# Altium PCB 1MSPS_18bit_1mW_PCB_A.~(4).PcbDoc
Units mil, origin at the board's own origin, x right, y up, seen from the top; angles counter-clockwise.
Board outline 3200 x 1700 mil, 4 copper layers (Top, Inner Layer 2, Inner Layer 3, Bottom), stack 35.4 mil thick; 66 components, 41 nets, 208 pads, 43 vias.
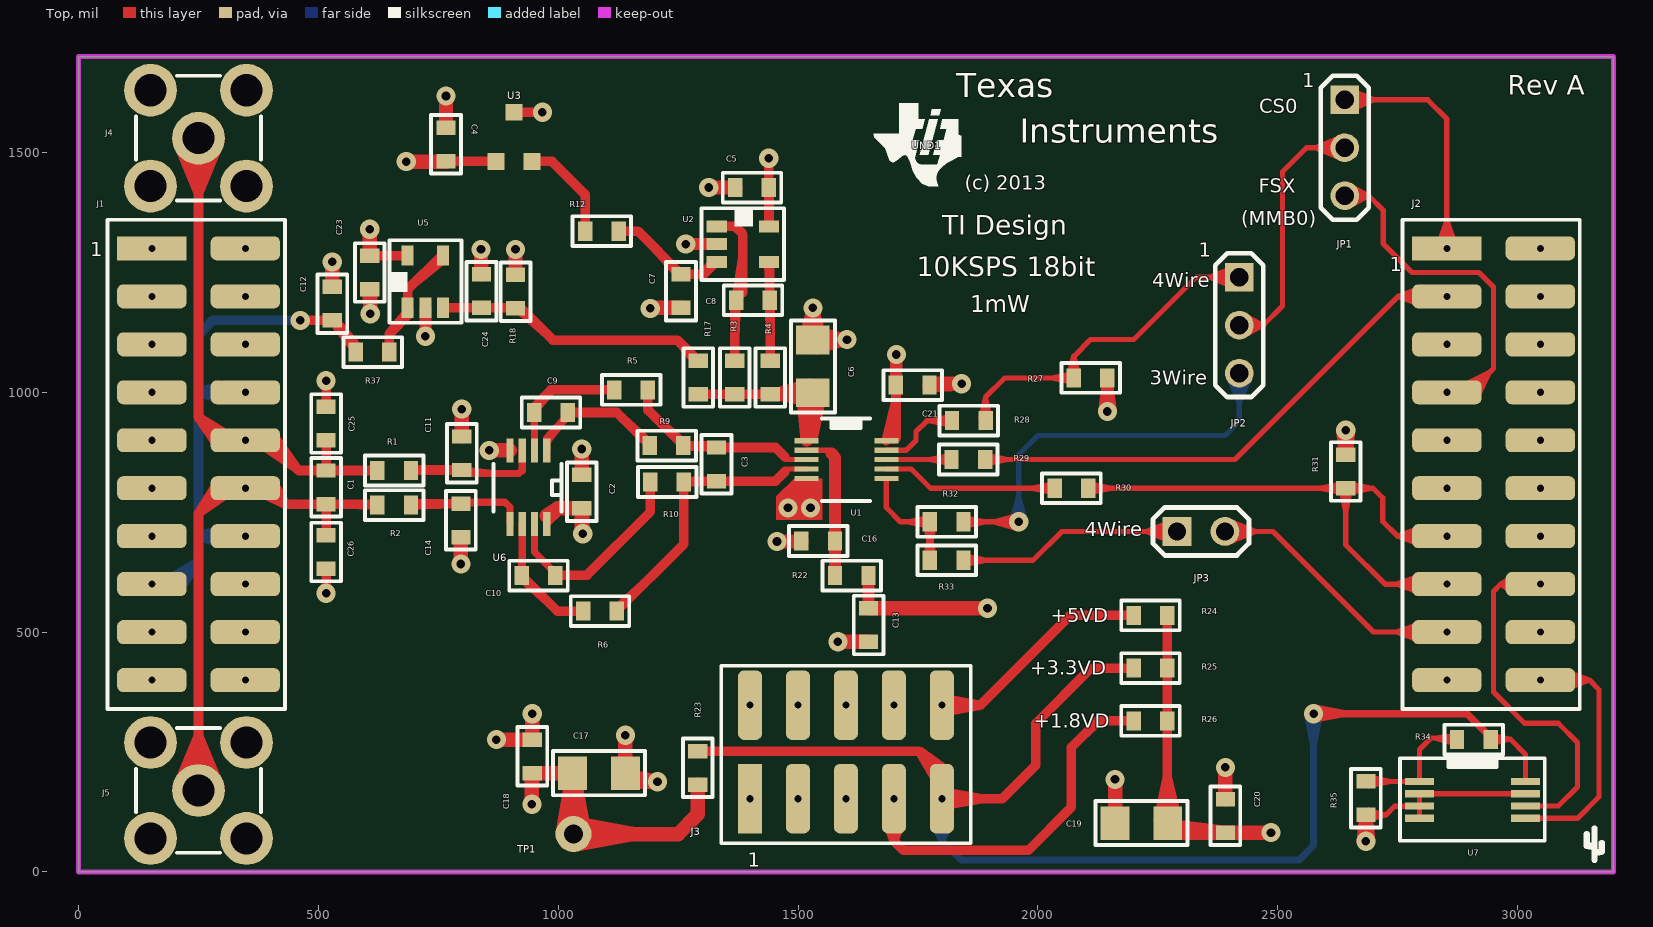
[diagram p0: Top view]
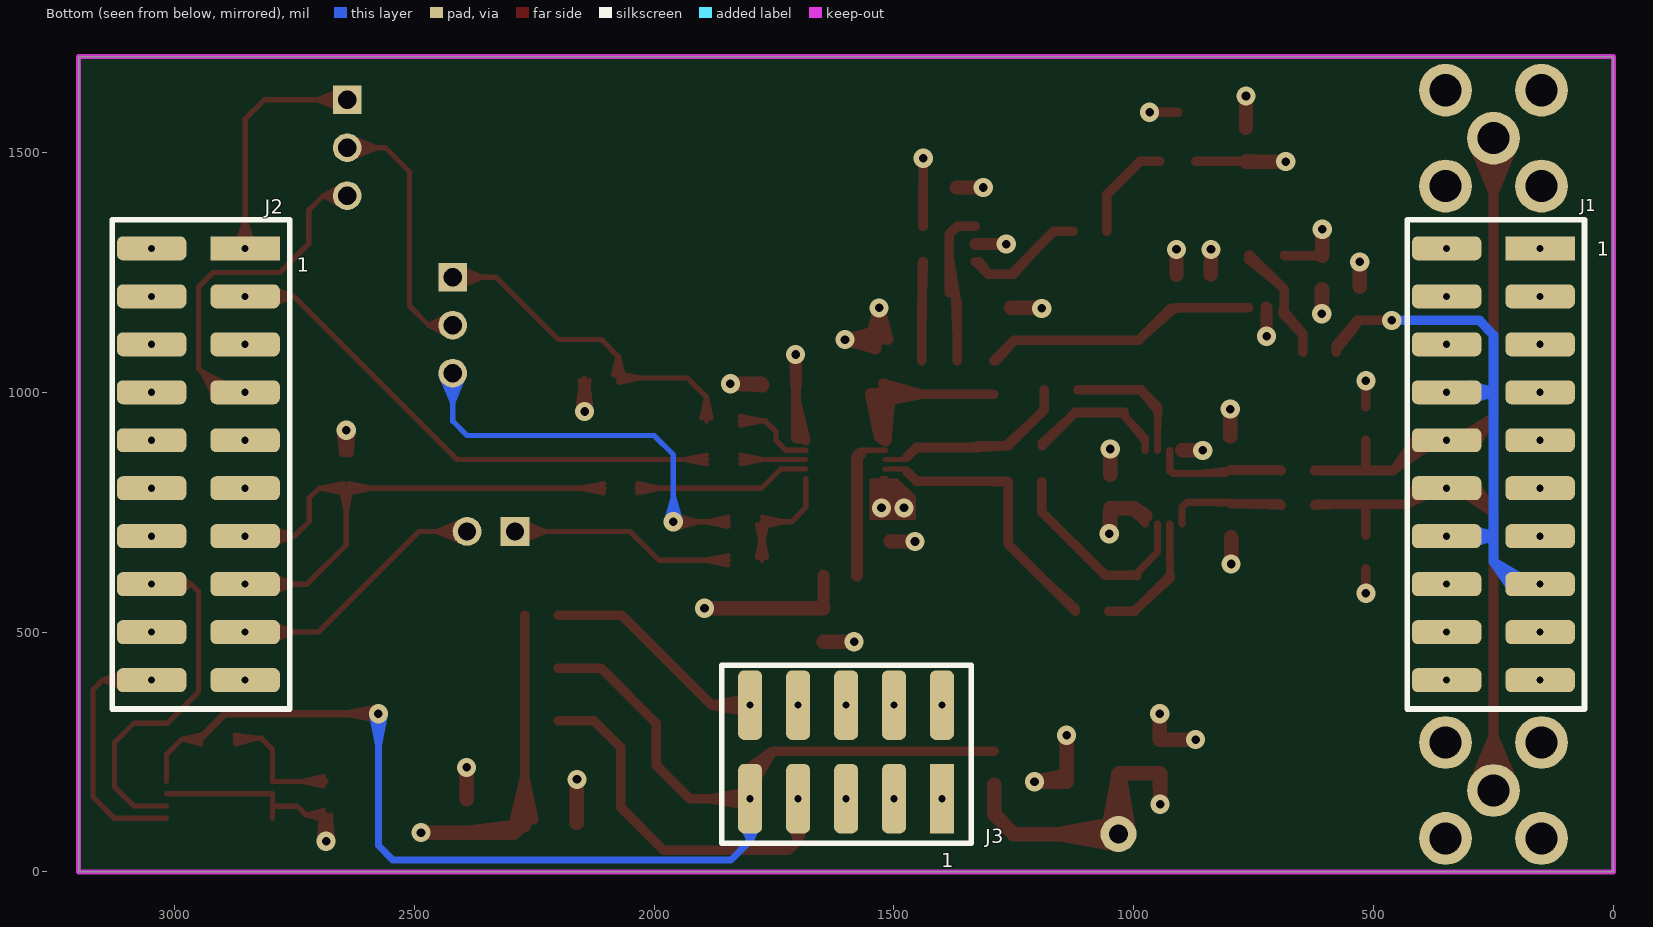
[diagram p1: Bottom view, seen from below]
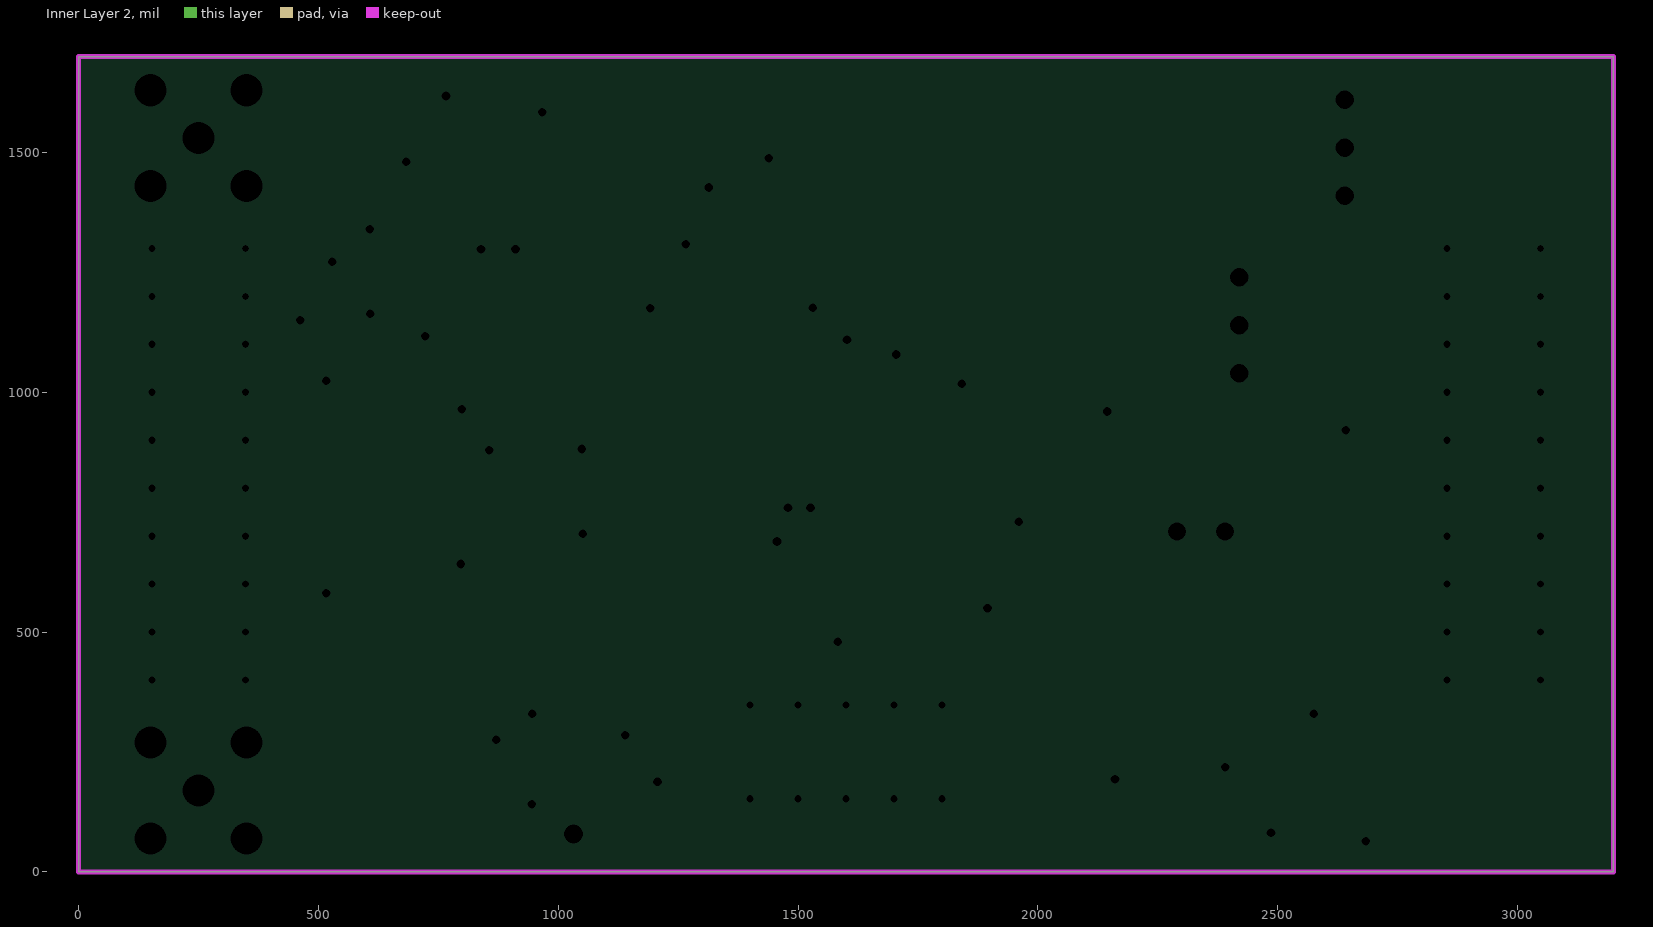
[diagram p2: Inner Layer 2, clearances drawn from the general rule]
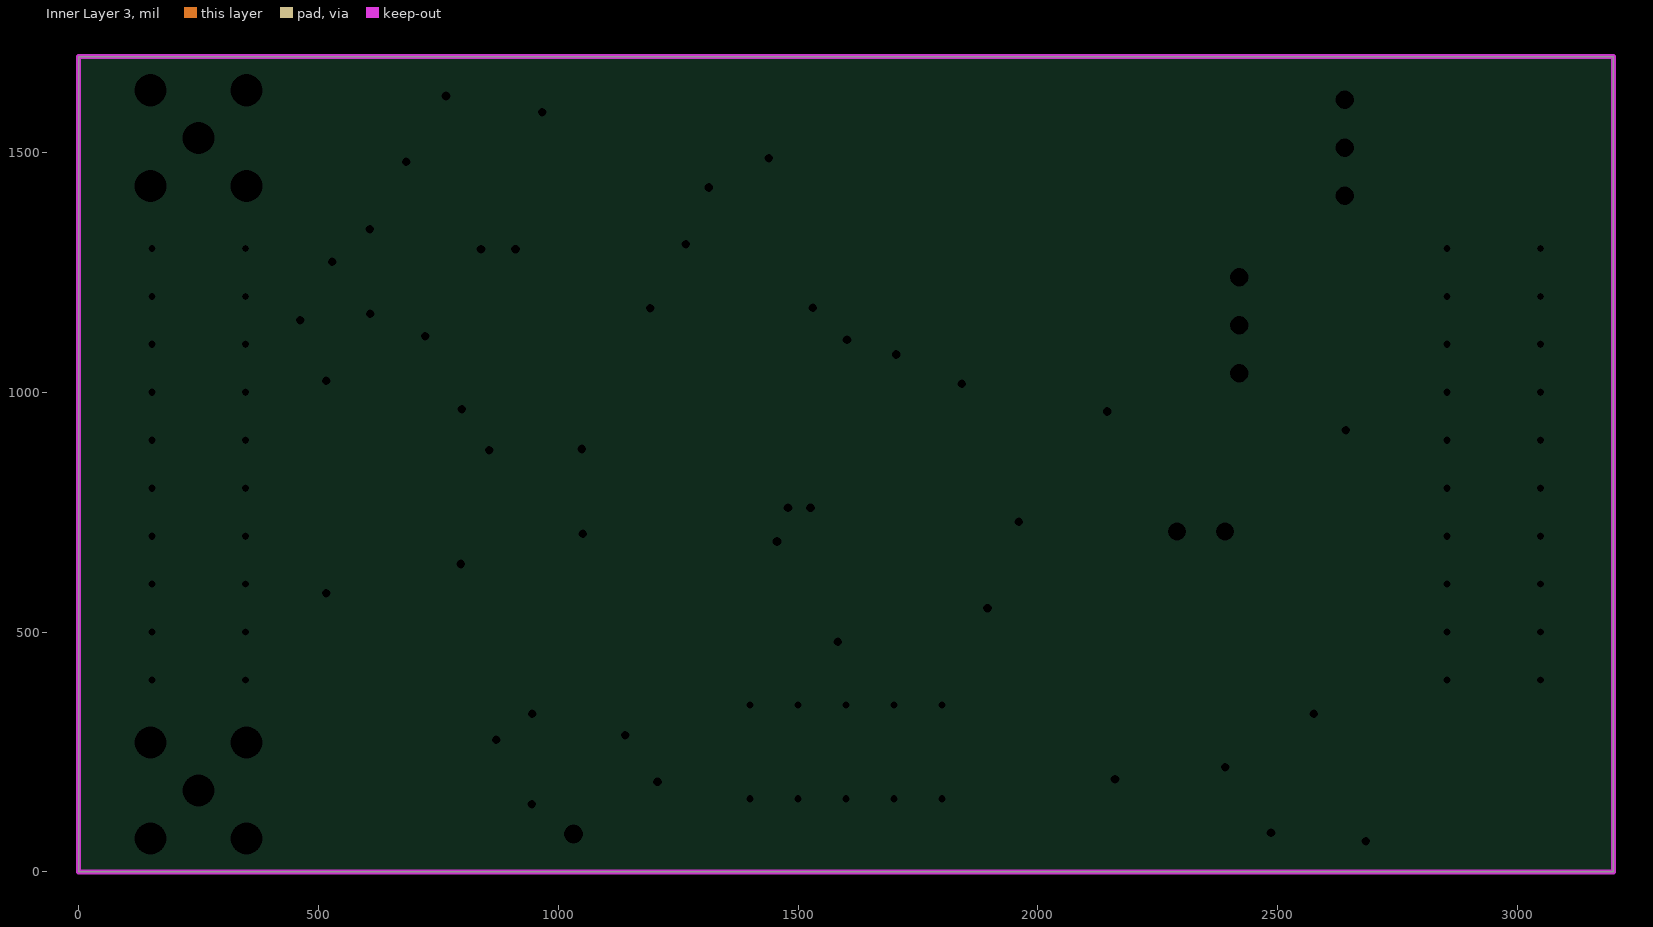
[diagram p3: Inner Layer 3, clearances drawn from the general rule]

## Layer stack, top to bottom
Top: signal copper 1.35
Dielectric: dielectric 10, FR-4, Dk 4.3
Inner Layer 2: plane copper 1.35
Dielectric: dielectric 10, FR-4, Dk 4.3
Inner Layer 3: plane copper 1.35
Dielectric: dielectric 10, FR-4, Dk 4.3
Bottom: signal copper 1.35

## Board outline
0,0 3200,0 3200,1700 0,1700

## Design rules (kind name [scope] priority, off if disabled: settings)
Clearance "'Default' PADS rule_18" [All] p1: gap=7
Clearance "'Default' PADS rule_15" [IsVia vs IsVia] p2: gap=7
ComponentClearance "'Default' PADS rule_12" [All] p1: gap=7 collisioncheckmode=3 verticalgap=10 showdistances=FALSE
FlightTimeFalling "'Default' PADS rule_10" [All] p1: maximum=10.00
FlightTimeRising "'Default' PADS rule_9" [All] p1: maximum=10.00
Length "'Default' PADS rule_5" [All] p1: maxlimit=50000 minlimit=0
MatchedLengths "'Default' PADS rule_11" [InNetClass('All Nets')] p1: tolerance=200 checknetsindiffpair=TRUE checkdiffpairvsdiffpair=TRUE checkothers=TRUE
MaxMinImpedance "'Default' PADS rule_8" [All] p1: minimum=50.00 maximum=150.0
ParallelSegment "'Default' PADS rule_7" [All] p1: limit=1000 gap=200
ParallelSegment "'Default' PADS rule_6" [All] p2: limit=1000 gap=200
PlaneClearance "'Default' PADS rule_14" [All] p1: clearance=7
PlaneConnect "Power Plane Connect Style for STDPCADVIA" [IsVia And (ViaDiameter=40) And (HoleSize=18)] p1: planeconnectstyle=Relief reliefexpansion=11 reliefentries=4 reliefconductorwidth=10 reliefairgap=10
PlaneConnect "Power Plane Connect Style for J3-5" [(Name='J3-5')] p2: planeconnectstyle=Relief reliefexpansion=7.5 reliefentries=4 reliefconductorwidth=20 reliefairgap=5
PlaneConnect "Power Plane Connect Style - pads with no thermal" [(Name='J2-2') Or (Name='J2-5') Or (Name='J2-6') Or (Name='J2-8') Or (Name='J2-9') Or (Name='J2-11') Or (Name='J2-12') Or (Name='J2-14') Or (Name='J2-19') Or (Name='J3-1') Or (Name='J3-2') Or (Name='J3-3') Or (Name='J3-4') Or (Name='J3-8') Or (Name='TP1-1')] p3: planeconnectstyle=NoConnect reliefexpansion=20 reliefentries=4 reliefconductorwidth=10 reliefairgap=10 // PAD - No Thermal Connect Rule
PlaneConnect "Power Plane Connect Style for J1-1" [(Name='J1-1')] p4: planeconnectstyle=Relief reliefexpansion=17.5 reliefentries=4 reliefconductorwidth=10 reliefairgap=10
PlaneConnect "Power Plane Connect Style - Via from round thru-hole global defaults" [IsVia] p5: planeconnectstyle=Relief reliefexpansion=20 reliefentries=4 reliefconductorwidth=10 reliefairgap=10
PlaneConnect "Power Plane Connect Style - Round thru-hole pad from global defaults" [IsPad And OnMultiLayer And (PadShape_MidLayer1 = 'Round') And (PadXSize_MidLayer1 = PadYSize_MidLayer1)] p6: planeconnectstyle=Relief reliefexpansion=20 reliefentries=4 reliefconductorwidth=10 reliefairgap=10
PlaneConnect "Power Plane Connect Style - Square thru-hole pad from global defaults" [IsPad And OnMultiLayer And ((PadShape_MidLayer1 = 'Rectangular') Or (PadShape_MidLayer1 = 'Octagonal') Or (PadShape_MidLayer1 = 'Rounded Rectangle')) And (PadXSize_MidLayer1 = PadYSize_MidLayer1)] p7: planeconnectstyle=Direct reliefexpansion=20 reliefentries=4 reliefconductorwidth=10 reliefairgap=10
PlaneConnect "Power Plane Connect Style - Rect thru-hole pad from global defaults" [IsPad And OnMultiLayer And ((PadShape_MidLayer1 = 'Rectangular') Or (PadShape_MidLayer1 = 'Octagonal') Or (PadShape_MidLayer1 = 'Rounded Rectangle')) And (PadXSize_MidLayer1 <> PadYSize_MidLayer1)] p8: planeconnectstyle=Direct reliefexpansion=20 reliefentries=4 reliefconductorwidth=10 reliefairgap=10
PlaneConnect "Power Plane Connect Style - Square-rect thru-hole pad from global defaults" [IsPad And OnMultiLayer And (PadShape_MidLayer1 = 'Rounded Rectangle') And (PadXSize_MidLayer1 = PadYSize_MidLayer1) And (Pad_CornerRadius_MidLayer1 = '0%')] p9: planeconnectstyle=Direct reliefexpansion=20 reliefentries=4 reliefconductorwidth=10 reliefairgap=10
PlaneConnect "Power Plane Connect Style - Oval thru-hole pad from global defaults" [IsPad And OnMultiLayer And (PadShape_MidLayer1 = 'Round') And (PadXSize_MidLayer1 <> PadYSize_MidLayer1)] p10: planeconnectstyle=Direct reliefexpansion=20 reliefentries=4 reliefconductorwidth=10 reliefairgap=10
PlaneConnect "Power Plane Connect Style - Round-oval thru-hole pad from global defaults" [IsPad And OnMultiLayer And (PadShape_MidLayer1 = 'Rounded Rectangle') And (PadXSize_MidLayer1 = PadYSize_MidLayer1) And (Pad_CornerRadius_MidLayer1 = '100%')] p11: planeconnectstyle=Direct reliefexpansion=20 reliefentries=4 reliefconductorwidth=10 reliefairgap=10
PolygonConnect "Polygon Connect Style - Bottom Round SMD from global defaults" [IsSMTPin And (PadShape_BottomLayer = 'Round') And (PadXSize_BottomLayer = PADYSize_BottomLayer) vs Layer = 'Bottom'] p1: connectstyle=Direct reliefconductorwidth=10 reliefentries=4 polygonreliefangle="45 Angle" airgapwidth=10
PolygonConnect "Polygon Connect Style - Top Round SMD from global defaults" [IsSMTPin And (PadShape_TopLayer = 'Round') And (PadXSize_TopLayer = PADYSize_TopLayer) vs Layer = 'Top'] p2: connectstyle=Direct reliefconductorwidth=10 reliefentries=4 polygonreliefangle="45 Angle" airgapwidth=10
PolygonConnect "Polygon Connect Style - Bottom Square SMD from global defaults 1" [IsSMTPin And (PadShape_BottomLayer = 'Rectangular') And (PadXSize_BottomLayer = PADYSize_BottomLayer) vs Layer = 'Bottom'] p3: connectstyle=Direct reliefconductorwidth=10 reliefentries=4 polygonreliefangle="45 Angle" airgapwidth=10
PolygonConnect "Polygon Connect Style - Bottom Square SMD from global defaults 2" [IsSMTPin And (PadShape_BottomLayer = 'Octagonal') And (PadXSize_BottomLayer = PADYSize_BottomLayer) vs Layer = 'Bottom'] p4: connectstyle=Direct reliefconductorwidth=10 reliefentries=4 polygonreliefangle="45 Angle" airgapwidth=10
PolygonConnect "Polygon Connect Style - Bottom Square SMD from global defaults 3" [IsSMTPin And (PadShape_BottomLayer = 'Rounded Rectangle') And (PadXSize_BottomLayer = PADYSize_BottomLayer) vs Layer = 'Bottom'] p5: connectstyle=Direct reliefconductorwidth=10 reliefentries=4 polygonreliefangle="45 Angle" airgapwidth=10
PolygonConnect "Polygon Connect Style - Top Square SMD from global defaults 1" [IsSMTPin And (PadShape_TopLayer = 'Rectangular') And (PadXSize_TopLayer = PADYSize_TopLayer) vs Layer = 'Top'] p6: connectstyle=Direct reliefconductorwidth=10 reliefentries=4 polygonreliefangle="45 Angle" airgapwidth=10
PolygonConnect "Polygon Connect Style - Top Square SMD from global defaults 2" [IsSMTPin And (PadShape_TopLayer = 'Octagonal') And (PadXSize_TopLayer = PADYSize_TopLayer) vs Layer = 'Top'] p7: connectstyle=Direct reliefconductorwidth=10 reliefentries=4 polygonreliefangle="45 Angle" airgapwidth=10
PolygonConnect "Polygon Connect Style - Top Square SMD from global defaults 3" [IsSMTPin And (PadShape_TopLayer = 'Rounded Rectangle') And (PadXSize_TopLayer = PADYSize_TopLayer) vs Layer = 'Top'] p8: connectstyle=Direct reliefconductorwidth=10 reliefentries=4 polygonreliefangle="45 Angle" airgapwidth=10
PolygonConnect "Polygon Connect Style - Bottom Rect SMD from global defaults 1" [IsSMTPin And (PadShape_BottomLayer = 'Rectangular') And (PadXSize_BottomLayer <> PADYSize_BottomLayer) vs Layer = 'Bottom'] p9: connectstyle=Direct reliefconductorwidth=10 reliefentries=4 polygonreliefangle="45 Angle" airgapwidth=10
PolygonConnect "Polygon Connect Style - Bottom Rect SMD from global defaults 2" [IsSMTPin And (PadShape_BottomLayer = 'Octagonal') And (PadXSize_BottomLayer <> PADYSize_BottomLayer) vs Layer = 'Bottom'] p10: connectstyle=Direct reliefconductorwidth=10 reliefentries=4 polygonreliefangle="45 Angle" airgapwidth=10
PolygonConnect "Polygon Connect Style - Bottom Rect SMD from global defaults 3" [IsSMTPin And (PadShape_BottomLayer = 'Rounded Rectangle') And (PadXSize_BottomLayer <> PADYSize_BottomLayer) vs Layer = 'Bottom'] p11: connectstyle=Direct reliefconductorwidth=10 reliefentries=4 polygonreliefangle="45 Angle" airgapwidth=10
PolygonConnect "Polygon Connect Style - Bottom Square-rect SMD pad from global defaults" [IsSMTPin And (PadShape_BottomLayer = 'Rounded Rectangle') And (PadXSize_BottomLayer = PADYSize_BottomLayer) And (Pad_CornerRadius_BottomLayer = '0%') vs Layer = 'Bottom'] p12: connectstyle=Direct reliefconductorwidth=10 reliefentries=4 polygonreliefangle="45 Angle" airgapwidth=10
PolygonConnect "Polygon Connect Style - Top Rect SMD from global defaults 1" [IsSMTPin And (PadShape_TopLayer = 'Rectangular') And (PadXSize_TopLayer <> PADYSize_TopLayer) vs Layer = 'Top'] p13: connectstyle=Direct reliefconductorwidth=10 reliefentries=4 polygonreliefangle="45 Angle" airgapwidth=10
PolygonConnect "Polygon Connect Style - Top Rect SMD from global defaults 2" [IsSMTPin And (PadShape_TopLayer = 'Octagonal') And (PadXSize_TopLayer <> PADYSize_TopLayer) vs Layer = 'Top'] p14: connectstyle=Direct reliefconductorwidth=10 reliefentries=4 polygonreliefangle="45 Angle" airgapwidth=10
PolygonConnect "Polygon Connect Style - Top Rect SMD from global defaults 3" [IsSMTPin And (PadShape_TopLayer = 'Rounded Rectangle') And (PadXSize_TopLayer <> PADYSize_TopLayer) vs Layer = 'Top'] p15: connectstyle=Direct reliefconductorwidth=10 reliefentries=4 polygonreliefangle="45 Angle" airgapwidth=10
PolygonConnect "Polygon Connect Style - Top Square-rect SMD pad from global defaults" [IsSMTPin And (PadShape_TopLayer = 'Rounded Rectangle') And (PadXSize_TopLayer = PADYSize_TopLayer) And (Pad_CornerRadius_TopLayer = '0%') vs Layer = 'Top'] p16: connectstyle=Direct reliefconductorwidth=10 reliefentries=4 polygonreliefangle="45 Angle" airgapwidth=10
PolygonConnect "Polygon Connect Style - Bottom Oval SMD from global defaults" [IsSMTPin And (PadShape_BottomLayer = 'Round') And (PadXSize_BottomLayer <> PADYSize_BottomLayer) vs Layer = 'Bottom'] p17: connectstyle=Direct reliefconductorwidth=10 reliefentries=4 polygonreliefangle="45 Angle" airgapwidth=10
PolygonConnect "Polygon Connect Style - Bottom Round-oval SMD pad from global defaults" [IsSMTPin And (PadShape_BottomLayer = 'Rounded Rectangle') And (PadXSize_BottomLayer = PADYSize_BottomLayer) And (Pad_CornerRadius_BottomLayer = '100%') vs Layer = 'Bottom'] p18: connectstyle=Direct reliefconductorwidth=10 reliefentries=4 polygonreliefangle="45 Angle" airgapwidth=10
PolygonConnect "Polygon Connect Style - Top Oval SMD from global defaults" [IsSMTPin And (PadShape_TopLayer = 'Round') And (PadXSize_TopLayer <> PADYSize_TopLayer) vs Layer = 'Top'] p19: connectstyle=Direct reliefconductorwidth=10 reliefentries=4 polygonreliefangle="45 Angle" airgapwidth=10
PolygonConnect "Polygon Connect Style - Top Round-oval SMD pad from global defaults" [IsSMTPin And (PadShape_TopLayer = 'Rounded Rectangle') And (PadXSize_TopLayer = PADYSize_TopLayer) And (Pad_CornerRadius_TopLayer = '100%') vs Layer = 'Top'] p20: connectstyle=Direct reliefconductorwidth=10 reliefentries=4 polygonreliefangle="45 Angle" airgapwidth=10
PolygonConnect "Polygon Connect Style - Via from round thru-hole global defaults_19" [IsVia] p21: connectstyle=Relief reliefconductorwidth=10 reliefentries=4 polygonreliefangle="90 Angle" airgapwidth=10
PolygonConnect "Polygon Connect Style - Bottom Round thru-hole pad from global defaults" [IsPad And OnMultiLayer And (PadShape_BottomLayer = 'Round') And (PadXSize_BottomLayer = PADYSize_BottomLayer) vs Layer = 'Bottom'] p22: connectstyle=Relief reliefconductorwidth=10 reliefentries=4 polygonreliefangle="90 Angle" airgapwidth=10
PolygonConnect "Polygon Connect Style - Via from round thru-hole global defaults" [IsVia] p23: connectstyle=Relief reliefconductorwidth=10 reliefentries=4 polygonreliefangle="90 Angle" airgapwidth=10
PolygonConnect "Polygon Connect Style - Top Round thru-hole pad from global defaults" [IsPad And OnMultiLayer And (PadShape_TopLayer = 'Round') And (PadXSize_TopLayer = PADYSize_TopLayer) vs Layer = 'Top'] p24: connectstyle=Relief reliefconductorwidth=10 reliefentries=4 polygonreliefangle="90 Angle" airgapwidth=10
PolygonConnect "Polygon Connect Style - Bottom Square thru-hole pad from global defaults" [IsPad And OnMultiLayer And ((PadShape_BottomLayer = 'Rectangular') Or (PadShape_BottomLayer = 'Octagonal') Or (PadShape_BottomLayer = 'Rounded Rectangle')) And (PadXSize_BottomLayer = PADYSize_BottomLayer) vs Layer = 'Bottom'] p25: connectstyle=Direct reliefconductorwidth=10 reliefentries=4 polygonreliefangle="45 Angle" airgapwidth=10
PolygonConnect "Polygon Connect Style - Top Square thru-hole pad from global defaults" [IsPad And OnMultiLayer And ((PadShape_TopLayer = 'Rectangular') Or (PadShape_TopLayer = 'Octagonal') Or (PadShape_TopLayer = 'Rounded Rectangle')) And (PadXSize_TopLayer = PADYSize_TopLayer) vs Layer = 'Top'] p26: connectstyle=Direct reliefconductorwidth=10 reliefentries=4 polygonreliefangle="45 Angle" airgapwidth=10
PolygonConnect "Polygon Connect Style - Bottom Rect thru-hole pad from global defaults" [IsPad And OnMultiLayer And ((PadShape_BottomLayer = 'Rectangular') Or (PadShape_BottomLayer = 'Octagonal') Or (PadShape_BottomLayer = 'Rounded Rectangle')) And (PadXSize_BottomLayer <> PADYSize_BottomLayer) vs Layer = 'Bottom'] p27: connectstyle=Direct reliefconductorwidth=10 reliefentries=4 polygonreliefangle="45 Angle" airgapwidth=10
PolygonConnect "Polygon Connect Style - Bottom Square-rect thru-hole pad from global defaults" [IsPad And OnMultiLayer And (PadShape_BottomLayer = 'Rounded Rectangle') And (PadXSize_BottomLayer = PADYSize_BottomLayer) And (Pad_CornerRadius_BottomLayer = '0%') vs Layer = 'Bottom'] p28: connectstyle=Direct reliefconductorwidth=10 reliefentries=4 polygonreliefangle="45 Angle" airgapwidth=10
PolygonConnect "Polygon Connect Style - Top Rect thru-hole pad from global defaults" [IsPad And OnMultiLayer And ((PadShape_TopLayer = 'Rectangular') Or (PadShape_TopLayer = 'Octagonal') Or (PadShape_TopLayer = 'Rounded Rectangle')) And (PadXSize_TopLayer <> PADYSize_TopLayer) vs Layer = 'Top'] p29: connectstyle=Direct reliefconductorwidth=10 reliefentries=4 polygonreliefangle="45 Angle" airgapwidth=10
PolygonConnect "Polygon Connect Style - Top Square-rect thru-hole pad from global defaults" [IsPad And OnMultiLayer And (PadShape_TopLayer = 'Rounded Rectangle') And (PadXSize_TopLayer = PADYSize_TopLayer) And (Pad_CornerRadius_TopLayer = '0%') vs Layer = 'Top'] p30: connectstyle=Direct reliefconductorwidth=10 reliefentries=4 polygonreliefangle="45 Angle" airgapwidth=10
PolygonConnect "Polygon Connect Style - Bottom Oval thru-hole pad from global defaults" [IsPad And OnMultiLayer And (PadShape_BottomLayer = 'Round') And (PadXSize_BottomLayer <> PADYSize_BottomLayer) vs Layer = 'Bottom'] p31: connectstyle=Direct reliefconductorwidth=10 reliefentries=4 polygonreliefangle="45 Angle" airgapwidth=10
PolygonConnect "Polygon Connect Style - Bottom Round-oval thru-hole pad from global defaults" [IsPad And OnMultiLayer And (PadShape_BottomLayer = 'Rounded Rectangle') And (PadXSize_BottomLayer = PADYSize_BottomLayer) And (Pad_CornerRadius_BottomLayer = '100%') vs Layer = 'Bottom'] p32: connectstyle=Direct reliefconductorwidth=10 reliefentries=4 polygonreliefangle="45 Angle" airgapwidth=10
PolygonConnect "Polygon Connect Style - Top Oval thru-hole pad from global defaults" [IsPad And OnMultiLayer And (PadShape_TopLayer = 'Round') And (PadXSize_TopLayer <> PADYSize_TopLayer) vs Layer = 'Top'] p33: connectstyle=Direct reliefconductorwidth=10 reliefentries=4 polygonreliefangle="45 Angle" airgapwidth=10
PolygonConnect "Polygon Connect Style - Top Round-oval thru-hole pad from global defaults" [IsPad And OnMultiLayer And (PadShape_TopLayer = 'Rounded Rectangle') And (PadXSize_TopLayer = PADYSize_TopLayer) And (Pad_CornerRadius_TopLayer = '100%') vs Layer = 'Top'] p34: connectstyle=Direct reliefconductorwidth=10 reliefentries=4 polygonreliefangle="45 Angle" airgapwidth=10
PolygonConnect [All] p35: connectstyle=Relief reliefconductorwidth=10 reliefentries=4 polygonreliefangle="90 Angle" airgapwidth=10
RoutingLayers "'Default' PADS rule_3" [All] p1: top layer_v5=TRUE bottom layer_v5=TRUE
RoutingPriority "'Default' PADS rule_2" [All] p1: routingpriority=3
RoutingTopology "'Default' PADS rule" [All] p1: topology=Shortest
RoutingVias "'Default' PADS rule_4" [All] p1: holewidth=37 width=55 viastyle="Through Hole" minholewidth=37 minwidth=55 maxholewidth=37 maxwidth=55
SMDToCorner "'Default' PADS rule_16" [All] p1: distance=70000
SMDToPlane "'Default' PADS rule_17" [All] p1: distance=70000
SilkscreenOverComponentPads [All] p1: minsilkscreentomaskgap=10
SolderMaskExpansion "Solder Mask Expansion from CAM settings" [All] p1: expansion=1
Width "'Default' PADS rule_13" [All] p1: maxlimit=30 minlimit=10 preferedwidth=20
21 further rules are at their usual default settings.

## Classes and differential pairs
net class CLASS_0: AGND

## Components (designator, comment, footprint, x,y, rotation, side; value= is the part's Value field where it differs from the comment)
C1 "C603" C603 516,802 r90 top
C2 "C603" C603 1049,793 r90 top
C3 "C603" C603 1330,850 r90 top
C4 "C603" C603 766,1517 r270 top
C5 "C603" C603 1404,1427 r180 top
C6 "C1206" C1206 1531,1054 r90 top
C7 "C603" C603 1256,1211 r90 top
C8 "C603" C603 1406,1192 r0 top
C9 "C603" C603 985,958 r0 top
C10 "C603" C603 959,618 r0 top
C11 "C603" C603 799,873 r270 top
C12 "C603" C603 529,1185 r270 top
C13 "C603" C603 1647,515 r90 top
C14 "C603" C603 797,733 r90 top
C16 "C603" C603 1542,690 r0 top
C17 "C1206" C1206 1085,206 r0 top
C18 "C603" C603 946,241 r270 top
C19 "C1206" C1206 2216,102 r180 top
C20 "C603" C603 2391,117 r270 top
C21 "C603" C603 1739,1015 r180 top
C23 "C603" C603 607,1250 r270 top
C24 "C603" C603 840,1211 r270 top
C25 "C603" C603 516,935 r270 top
C26 "C603" C603 516,667 r90 top
J1 "HEADER_TSM-110-XX-DV_TH" HEADER_TSM-110-XX-DV_TH 250,850 r270 top
J2 "HEADER_TSM-110-XX-DV_TH" HEADER_TSM-110-XX-DV_TH 2950,850 r270 top
J3 "HEADER_TSM-105-XX-DV_THA" HEADER_TSM-105-XX-DV_THA 1600,250 r0 top
J4 "CONNECTOR_SMA" CONNECTOR_SMA 250,1530 r0 top
J5 "CONNECTOR_SMA" CONNECTOR_SMA 250,170 r0 top
JP1 "HDR100_1X3" HDR100_1X3 2640,1610 r270 top
JP2 "HDR100_1X3" HDR100_1X3 2420,1240 r270 top
JP3 "HDR100_1X2" HDR100_1X2 2290,710 r0 top
R1 "R0603" R0603 658,837 r180 top
R2 "R0603" R0603 658,765 r180 top
R3 "R0603" R0603 1368,1031 r270 top
R4 "R0603" R0603 1442,1031 r270 top
R5 "R0603" R0603 1152,1005 r0 top
R6 "R0603" R0603 1087,544 r0 top
R9 "R0603" R0603 1226,889 r0 top
R10 "R0603" R0603 1227,813 r0 top
R12 "R0603" R0603 1091,1336 r0 top
R17 "R0603" R0603 1292,1031 r270 top
R18 "R0603" R0603 911,1210 r90 top
R22 "R0603" R0603 1612,618 r180 top
R23 "R0603" R0603 1291,217 r90 top
R24 "R0603" R0603 2235,535 r0 top
R25 "R0603" R0603 2235,425 r0 top
R26 "R0603" R0603 2235,315 r0 top
R27 "R0603" R0603 2110,1030 r180 top
R28 "R0603" R0603 1856,941 r0 top
R29 "R0603" R0603 1855,860 r0 top
R30 "R0603" R0603 2070,800 r0 top
R31 "R0603" R0603 2642,835 r270 top
R32 "R0603" R0603 1810,730 r0 top
R33 "R0603" R0603 1810,650 r0 top
R34 "R0603" R0603 2909,276 r0 top
R35 "R0603" R0603 2684,154 r270 top
R37 "R0603" R0603 613,1084 r180 top
TP1 "TH-40" TH-40 1032,79 r0 top
U1 "DGS_10P" DGS_10P 1600,860.25 r0 top
U2 "DBV-5" DBV-5 1385,1309 r0 top
U3 "SOT-23" SOT-23 908,1534 r0 top
U5 "DBV-5" DBV-5 723,1231 r90 top
U6 "DGK8" DGK8 936,801 r270 top
U7 "TSSOP8" TSSOP8 2906,151 r0 top
UND1 "TIBUG2-NEW" TIBUG2-NEW 1761,1514 r0 top

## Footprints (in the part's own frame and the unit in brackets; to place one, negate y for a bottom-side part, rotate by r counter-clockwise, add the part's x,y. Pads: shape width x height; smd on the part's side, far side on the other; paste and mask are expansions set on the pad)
C603 [mil]
  rect 30x40 smd mask+2: 1(-35,0) 2(35,0)
  silkscreen extent -61,-31 61,31
C1206 [mil]
  rect 60x70 smd mask+2: 1(-55,0) 2(55,0)
  silkscreen extent -96,-46 96,46
CONNECTOR_SMA [mil]
  round 110 hole 67 mask+2.5: 1(0,0) 2(100,100) 3(100,-100) 4(-100,-100) 5(-100,100)
  silkscreen extent -130,-130 130,130
DBV-5 [mil]
  rect 42x25 smd mask+1.5: 1(-54.5,37) 2(-54.5,0) 3(-54.5,-37) 4(54.5,-37) 5(54.5,37)
  silkscreen extent -86,-75 86,75
DGK8 [mil]
  rect 50x15 smd mask+1.5: 1(-78,40) 2(-78,14.4) 3(-78,-11.2) 4(-78,-36.8) 5(75.6,-36.8) 6(75.6,-11.2) 7(75.6,14.4) 8(75.6,40)
  silkscreen extent -50,-71 50,71
DGS_10P [mil]
  rect 50x11 smd mask+1.5: 1(-82,39) 2(-82,19.3) 3(-82,-0.4) 4(-82,-20.1) 5(-82,-39.8) 6(84,-39.8) 7(84,-20.1) 8(84,-0.4) 9(84,19.3) 10(84,39)
  silkscreen extent -50,-87 50,85
HDR100_1X2 [mil]
  rect 60x60 hole 38 mask+2.5: 1(0,0)
  round 60 hole 38 mask+2.5: 2(100,0)
  silkscreen extent -50,-50 150,50
HDR100_1X3 [mil]
  rect 60x60 hole 38 mask+2.5: 1(0,0)
  round 60 hole 38 mask+2.5: 2(100,0) 3(200,0)
  silkscreen extent -50,-50 250,50
HEADER_TSM-105-XX-DV_THA [mil]
  rect 50x145 hole 15 mask+2.5: 1(-200.1,-97.2)
  rrect50% 50x145 hole 15 mask+2.5: 2(-200.1,97.8) 3(-100.1,-97.2) 4(-100.1,97.8) 5(-0.1,-97.2) 6(-0.1,97.8) 7(99.9,-97.2) 8(99.9,97.8) 9(199.9,-97.2) 10(199.9,97.8)
  silkscreen extent -260,-190 260,180
HEADER_TSM-110-XX-DV_TH [mil]
  rect 50x145 hole 15 mask+2.5: 1(-450.1,-97.2)
  rrect50% 50x145 hole 15 mask+2.5: 2(-450.1,97.8) 3(-350.1,-97.2) 4(-350.1,97.8) 5(-250.1,-97.2) 6(-250.1,97.8) 7(-150.1,-97.2) 8(-150.1,97.8) 9(-50.1,-97.2) 10(-50.1,97.8) 11(49.9,-97.2) 12(49.9,97.8) 13(149.9,-97.2) 14(149.9,97.8) 15(249.9,-97.2) 16(249.9,97.8) 17(349.9,-97.2) 18(349.9,97.8) 19(449.9,-97.2) 20(449.9,97.8)
  silkscreen extent -510,-190 510,180
R0603 [mil]
  rect 30x40 smd mask+2: 1(-35,0) 2(35,0)
  silkscreen extent -61,-31 61,31
SOT-23 [mil]
  rect 35x35 smd: 1(-37.5,-52.5) 2(37.5,-52.5) 3(0,50)
TH-40 [mil]
  round 75 hole 40 mask+2.5: 1(0,0)
TIBUG2-NEW [mil]
  silkscreen extent -103,-84 79,89
TSSOP8 [mil]
  rect 60x15 smd mask+1.5: 1(-110.1,37.6) 2(-110.1,12) 3(-110.1,-13.6) 4(-110.1,-39.2) 5(110.9,-39.2) 6(110.9,-13.6) 7(110.9,12) 8(110.9,37.6)
  silkscreen extent -151,-86 151,86

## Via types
v1: diameter 40/40 (per signal layer), hole 18, Top to Bottom, 43 vias

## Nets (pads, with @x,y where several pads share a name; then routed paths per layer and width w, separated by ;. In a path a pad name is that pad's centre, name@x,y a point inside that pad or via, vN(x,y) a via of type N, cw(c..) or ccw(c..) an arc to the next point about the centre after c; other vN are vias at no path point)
$$$2464: C7.2 R12.2 U2.3 | length 404.5
  Top w20: R12.2 1166,1336 C7.2 1303,1246 ; 1198.57,1303.43 C7.2@1251,1246 ; C7.2@1261,1246 1303,1246 ; U2.3@1322,1272 1303,1246 ; U2.3 1329,1272 1303,1246
$$$7948: C16.2 R22.2 U1.2 | length 631.3
  Top w11: U1.2 1568,879.55 ; U1.2@1537.5,879.55 1568,879.55 ; 1570,873 1570,877.55 1568,879.55 ; C16.2 C16.2@1577,696
  Top w25: 1570,873 1577,864 C16.2@1577,696 ; C16.2@1577,695 1577,785 ; R22.2 C16.2 1577,623 1577,685 R22.2
$$$13081: R12.1 U3.2 | length 287.1
  Top w20: U3.2 987,1481.5 1056,1412.5 ; R12.1 1056,1412.5 ; R12.1@1056,1341 1056,1412.5
$$$14370: C8.1 R3.1 U2.1 | length 500.4
  Top w20: U2.1 1369,1346 ; U2.1@1339,1346 1369,1346 ; R3.1 1368,1189 C8.1 ; 1368,1111.81 C8.1@1371,1187 ; C8.1@1371,1197 1385,1280.62 ; C8.1@1385,1208 1385,1330 1369,1346
$$$14376: R37.1 U5.1 U5.4 | length 444.5
  Top w20: R37.1 648,1122 ; R37.1@648,1089 648,1122 ; U5.1@686,1168 648,1122 ; U5.1@686,1185 686,1214 ; 703.99,1231.99 U5.4@760,1277 ; U5.4 757.5,1285.5 686,1214 ; 648,1122 688,1162 688,1174.5 U5.1 686,1214
$$$15592: C10.1 R6.1 U6.6 | length 456.7
  Top w15: C10.1 924.8,618.8 U6.6 ; C10.1@924,623 924.8,683.01 ; 924.8,655.4 U6.6@924.8,707.9
  Top w20: C10.1@924,613 981.43,560.57 ; C10.1 998,544 R6.1
$$$15636: C8.2 R4.1 U2.4 | length 503.2
  Top w20: C8.2@1441,1187 1442,1111.98 ; C8.2@1441,1199.43 U2.4 ; R4.1 1442,1191 C8.2 U2.4@1441,1270.5 ; U2.4 U2.4@1441,1270.5 ; U2.4 1441,1197 U2.4@1441,1270.5
$$$15662: C6.1 R3.2 R4.2 R17.2 U1.1 | length 2006.6
  Top w11: U1.1 1529,899.25 1529,907 U1.1
  Top w20: C6.1@1522,996 R4.2@1447,996 ; C6.1@1522.72,1018.73 R4.2@1447,996 ; C6.1@1522.91,1018.76 R4.2 ; C6.1@1524.22,979.08 R4.2@1447,996 ; C6.1@1524.33,979.07 R4.2 ; C6.1@1529,977 1529,992 1531,994 C6.1@1531,996 ; C6.1 C6.1@1531,996 ; R3.2 R17.2 1363,996 1297,996 R3.2 ; R3.2 R4.2 ; R3.2 1437,996 1373,996 R4.2 ; R4.2 C6.1@1531,996 ; R4.2 1526,999 R4.2@1447,996
  Top w25: C6.1@1508.5,998.87 U1.1 ; C6.1@1513.55,997.72 1529,907 ; C6.1@1526,999 U1.1 ; C6.1 1529,907 ; C6.1@1543.25,996.08 U1.1 ; C6.1@1548.38,996.96 1529,907 ; U1.1 1529,977 1529,907 ; U1.1 1529,907
$$$16005: C9.1 R5.1 U6.2 | length 496.3
  Top w15: C9.1 950.4,957.6 U6.2 ; U6.2@950.4,893 950,953 950.4,896.5 C9.1@950.4,949
  Top w20: C9.1 950,970 985,1005 ; C9.1@950,963 985,1005 ; R5.1 985,1005
$$$16016: C9.2 R9.1 U6.1 | length 576.9
  Top w15: U6.1 976,905 ; U6.1@979.01,900.28 1020,953 976,905 ; C9.2@1009.33,938.33 U6.1@976,896.5 ; C9.2 1019,957 1019,948 976,905 ; U6.1@976,896.5 976,905 ; U6.1@976,896.5 976,905
  Top w20: C9.2 1122,958 R9.1 ; 1133.57,946.43 R9.1@1191,894
$$$16459: C10.2 R10.1 U6.7 | length 665.8
  Top w15: U6.7@950.4,707.9 950.4,667 ; U6.7 950.4,667 ; C10.2@994,623 950.4,667 ; C10.2@995,619 995,622.4 950.4,667
  Top w20: R10.1@1192,808 1192,751 ; R10.1 1192,751 ; 1060,619 1192,751 ; 1060,619 995,619 C10.2 1060,619
$$$17367: J2.17 JP3.2 | length 1091.7
  Top w11: JP3.2 2490.1,710 2700,500.1 J2.17 ; JP3.2@2391.45,696.58 2453,710 ; JP3.2@2391.45,723.42 2453,710 ; JP3.2@2394.76,685.97 2453,710 ; JP3.2@2394.76,734.03 2453,710 ; J2.17@2802.02,480.88 2747.3,500.1 ; J2.17@2802.02,519.32 2747.3,500.1 ; J2.17@2804.68,491.62 2747.3,500.1 ; J2.17@2804.68,508.58 2747.3,500.1 ; J2.17@2805.3,500.1 2747.3,500.1
$$$17384: J2.3 R29.2 | length 1470.7
  Top w11: R29.2 2411,860 2751.1,1200.1 ; R29.2@1890.94,850.55 1938,860 R29.2@1890.94,869.45 ; J2.3@2801.79,1180.92 2751.1,1200.1 ; J2.3@2801.79,1219.28 2751.1,1200.1 ; J2.3@2804.63,1191.63 2751.1,1200.1 ; J2.3@2804.63,1208.57 2751.1,1200.1 ; J2.3@2805.3,1200.1 2751.1,1200.1 ; J2.3 2751.1,1200.1
$$$17558: J2.7 JP1.3 | length 1206.7
  Top w11: JP1.3 2690,1410 ; JP1.3@2641.82,1396.62 2690,1410 ; JP1.3@2641.82,1423.38 2690,1410 ; JP1.3@2646,1386.25 2690,1410 ; JP1.3@2646,1433.75 2690,1410 ; J2.7 2900,1000.1 2950,1050.1 2950,1220 2920,1250 2780,1250 2720,1310 2720,1380 2690,1410 ; J2.7@2888.98,1015.97 2941.04,1041.14 ; J2.7@2894.72,1006.52 2941.04,1041.14 ; J2.7@2900.3,1000.1 2941.04,1041.14 ; J2.7@2906.76,994.57 2941.04,1041.14 ; J2.7@2916.26,988.89 2941.04,1041.14
$$$17563: J2.1 JP1.1 | length 983.3
  Top w11: JP1.1 2812.8,1610 2852.8,1570 J2.1 ; JP1.1@2641.45,1596.58 2703,1610 ; JP1.1@2641.45,1623.42 2703,1610 ; JP1.1@2644.76,1585.97 2703,1610 ; JP1.1@2644.76,1634.03 2703,1610 ; J2.1@2833.58,1303.38 2852.8,1358.1 ; J2.1@2844.32,1300.72 2852.8,1358.1 ; J2.1@2861.28,1300.72 2852.8,1358.1 ; J2.1@2872.02,1303.38 2852.8,1358.1
$$$19122: C3.2 R5.2 R9.2 U1.3 | length 699.7
  Top w11: 1472,866 1472,859.85 ; U1.3@1498.5,859.85 1472,859.85 ; U1.3 1472,859.85
  Top w20: R5.2@1187,1000 1187,963 ; R5.2 1187,963 ; 1203.57,946.43 R9.2@1261,894 ; C3.2@1325,885 R9.2 ; C3.2@1335,885 1410,885 ; 1472,866 1453,885 C3.2 1326,889 R9.2 ; 1187,963 R9.2
$$$19127: C3.1 R6.2 R10.2 U1.4 | length 1044.2
  Top w11: 1472,834 1472,840 ; U1.4@1498.5,840.15 1472,840 ; U1.4 1518,840 1472,840
  Top w20: R6.2 1262,684 R10.2 ; R6.2@1122,549 1179.43,601.43 ; 1262,733 R10.2@1262,808 ; C3.1@1335,815 1410,815 ; 1472,834 1453,815 C3.1 ; R10.2 R10.2@1264,815 ; R10.2 C3.1 ; R10.2 1325,815 R10.2@1264,815 ; R10.2@1264,815 C3.1
$$$21346: C24.2 R17.1 R18.1 U5.3 | length 1131.9
  Top w20: C24.2@832.51,1176 U5.3 ; R18.1@916,1175 976.78,1121.22 ; R17.1@1287,1066 1249,1109 ; R17.1 1249,1109 ; U5.3 U5.3@760.5,1176 ; U5.3 835,1176 U5.3@760.5,1176 ; U5.3@760.5,1176 C24.2 ; C24.2 R18.1@911,1176 ; C24.2 906,1175 845,1176 R18.1@911,1176 ; R18.1@911,1176 R18.1 923,1175 989,1109 1249,1109
$$$22242: J2.16 U7.6 | length 966.3
  Top w11: J2.16@2994.9,581.36 2965.1,600.1 ; J2.16@2994.9,618.84 2965.1,600.1 ; J2.16@2999.27,591.66 2965.1,600.1 ; J2.16@2999.27,608.54 2965.1,600.1 ; J2.16@3000.3,600.1 2965.1,600.1 ; U7.6 3085,137.4 3125,177.4 3125,270 3085,310 3015,310 2950,375 2950,585 2965.1,600.1 ; U7.6@3039.4,137.4 3079.9,137.4 ; J2.16 2965.1,600.1
$$$22255: J2.20 U7.5 | length 839
  Top w11: U7.5 3125,111.8 3170,156.8 3170,380 3149.9,400.1 ; U7.5@3039.4,111.8 3079.9,111.8 ; J2.20 3149.9,400.1 ; J2.20@3095.3,400.1 3149.9,400.1 ; J2.20@3095.96,391.63 3149.9,400.1 ; J2.20@3095.96,408.57 3149.9,400.1 ; J2.20@3098.78,380.91 3149.9,400.1 ; J2.20@3098.78,419.29 3149.9,400.1
$$$22414: R34.1 R35.1 U7.1 | length 597.3
  Top w11: R35.1 2684.4,188.6 U7.1 2795.9,255 2820,279.1 2870.9,279.1 R34.1 2825.79,279.1 ; R35.1@2689,189 2737,188.6 ; R35.1@2689.86,179.54 2737,188.6 ; R35.1@2690.02,198.45 2737,188.6 ; 2732.9,188.6 U7.1@2773.4,188.6 ; R34.1@2872.46,266.63 2825.79,279.1 ; R34.1@2873.67,285.49 2825.79,279.1
$$$23087: JP2.1 R27.2 R28.2 | length 1307.9
  Top w11: R28.2@1881.56,947.03 1891,990 ; R28.2 1891,990 ; R28.2@1891,946 1891,990 ; R28.2@1900.44,947.03 1891,990 ; R27.2@2065.57,1036.13 2075,1075 ; R27.2@2074.06,1020.55 2027,1030 R27.2@2074.06,1039.45 ; R27.2@2075,1035 2075,1075 ; R27.2@2084.43,1036.13 2075,1075 ; JP2.1@2415.24,1215.97 2357,1240 ; JP2.1@2415.24,1264.03 2357,1240 ; JP2.1@2418.55,1226.58 2357,1240 ; JP2.1@2418.55,1253.42 2357,1240 ; JP2.1 2330,1240 2200,1110 2110,1110 2075,1075 ; 1891,990 1931,1030 R27.2 2075,1075
$$$23256: JP1.2 JP2.2 | length 989.3
  Top w11: JP2.2 2470,1140 ; JP2.2@2421.82,1126.62 2470,1140 ; JP2.2@2421.82,1153.38 2470,1140 ; JP2.2@2426,1116.25 2470,1140 ; JP2.2@2426,1163.75 2470,1140 ; JP1.2@2635.24,1485.97 2577,1510 ; JP1.2@2635.24,1534.03 2577,1510 ; JP1.2@2638.55,1496.58 2577,1510 ; JP1.2@2638.55,1523.42 2577,1510 ; JP1.2 2560,1510 2510,1460 2510,1180 2470,1140
$$$23301: R28.1 U1.9 | length 339.8
  Top w11: U1.9 1726,879.55 ; U1.9@1703.5,879.55 1726,879.55 ; R28.1@1819.97,950.44 1773,940.55 ; R28.1@1820.15,931.54 1773,940.55 ; 1726,879.55 1746,899.55 1746,918 1768.55,940.55 1820.55,940.55 R28.1 1773,940.55
$$$23343: R29.1 U1.8 | length 318.7
  Top w11: U1.8 1820,859.85 R29.1 1772,859.85 ; U1.8@1703.5,859.85 1742,859.85 ; R29.1@1819.03,869.45 1772,859.85 ; R29.1@1819.09,850.54 1772,859.85
$$$23357: R30.1 U1.7 | length 496.1
  Top w11: U1.7 1736,840.15 ; U1.7@1703.5,840.15 1736,840.15 ; R30.1@2034.06,790.55 1987,800 R30.1@2034.06,809.45 ; R30.1 1776.15,800 1736,840.15
$$$23386: JP2.3 R32.2 | length 1404
  Top w11: R32.2 v1(1960,730) ; R32.2@1845.94,720.55 1893,730 R32.2@1845.94,739.45 ; v1@1958.02,715.64 1907,730 v1@1958.02,744.36
  Bottom w11: v1@1945.64,731.98 1960,783 v1@1974.36,731.98 ; v1(1960,730) 1960,870 2000,910 2390,910 2420,940 JP2.3 ; JP2.3@2395.97,1035.24 2420,977 ; JP2.3@2406.58,1038.55 2420,977 ; JP2.3@2433.42,1038.55 2420,977 ; JP2.3@2444.03,1035.24 2420,977
$$$23391: R32.1 R33.1 U1.6 | length 627.9
  Top w11: U1.6 1684,760 1714,730 R32.1 R33.1 ; R33.1@1765.55,655.94 1775,703 ; R32.1@1765.55,724.06 1775,677 ; R32.1@1774.06,720.55 1727,730 R32.1@1774.06,739.45 ; R33.1@1775,655 1775,703 ; R32.1@1775,725 1775,677 ; R33.1@1784.45,655.94 1775,703 ; R32.1@1784.45,724.06 1775,677
$$$23695: JP3.1 R33.2 | length 817.9
  Top w11: R33.2 1990,650 2050,710 JP3.1 ; R33.2@1845.94,640.55 1893,650 R33.2@1845.94,659.45 ; JP3.1@2285.24,685.97 2227,710 ; JP3.1@2285.24,734.03 2227,710 ; JP3.1@2288.55,696.58 2227,710 ; JP3.1@2288.55,723.42 2227,710
$$$23868: J2.13 J2.15 R30.2 R31.2 | length 2227
  Top w11: R30.2 R31.2 ; R30.2@2105.94,790.55 2153,800 R30.2@2105.94,809.45 ; R31.2@2632.55,799.06 2642,752 R31.2@2651.45,799.06 ; R31.2@2636.06,790.55 2589,800 ; R31.2@2636.06,809.45 2589,800 ; R31.2@2637,800 2589,800 ; R31.2@2647,800 2695,800 ; R31.2@2647.94,790.55 2695,800 ; R31.2@2647.94,809.45 2695,800 ; J2.13@2801.86,680.91 2750,700.1 ; J2.13@2801.86,719.29 2750,700.1 ; J2.15@2802.02,580.88 2747.3,600.1 ; J2.15@2802.02,619.32 2747.3,600.1 ; J2.13@2804.65,691.63 2750,700.1 ; J2.13@2804.65,708.57 2750,700.1 ; J2.15@2804.68,591.62 2747.3,600.1 ; J2.15@2804.68,608.58 2747.3,600.1 ; J2.15@2805.3,600.1 2747.3,600.1 ; J2.13@2805.3,700.1 2750,700.1 ; J2.15 2724,600.1 2642,682.1 R31.2 ; J2.13 2750,700.1 ; R31.2 2699,800 2719,780 2719,731.1 2750,700.1
$$$31818: C14.2 R2.1 U6.5 | length 575.9
  Top w15: C14.2 800,771 889.2,771 899.2,761 ; C14.2@802,768 862.16,771 ; U6.5 899.2,761 ; U6.5@899.2,742.9 899.2,761
  Top w20: 716.94,765.95 C14.2@792,768 ; 717,768 C14.2@792,768 ; C14.2 696,768 R2.1 768.27,768 C14.2@792,768
$$$31881: C11.2 R1.1 U6.3 | length 517.2
  Top w15: C11.2 806.8,831 917.8,831 922.8,836 924.8,836 ; C11.2@804,838 865.32,831 ; U6.3@924.8,861.5 924.8,836 ; U6.3 924.8,836
  Top w20: 719,838 C11.2@794,838 ; 768.03,838 R1.1 694,838 C11.2
+1.8VD: J3.7 R26.1 | length 977.1
  Top w20: J3.7@1685.16,102.51 1699.9,65 ; J3.7@1699.9,105.3 1699.9,65 ; J3.7 1699.9,65 ; J3.7@1714.64,102.51 1699.9,65 ; 1699.9,65 1719.9,45 1980,45 2070,135 2070,260 2125,315 ; 2125,315 R26.1 2125,315
+3.3VD: J3.9 R23.2 R25.1 R34.2 U7.8 | length 3870.9
  Top w11: R34.2@2944,281 R34.2 ; R34.2@2944.89,285.46 2985,276.9 ; R34.2@2945.31,266.59 2985,276.9 ; U7.8 3016.9,245 2985,276.9 ; R34.2 2944.9,276.9 2985,276.9 ; R34.2 2985,276.9
  Top w15: v1(2575,330) 2895,330 2944,281 2898.8,326.2 ; v1@2576.2,317.56 2640,330 v1@2576.2,342.44
  Top w20: R23.2 1753,252 ; R23.2@1296,252 1371,252 ; J3.9@1787.77,191.47 1753,252 ; J3.9@1799.9,200.3 1753,252 ; J3.9@1801.22,137.86 1884.9,152.8 J3.9@1801.22,167.74 ; J3.9@1809.86,211.51 1753,252 ; R25.1 2111,425 1996,310 1996,222.8 1926,152.8 J3.9 1799.9,205.1 1753,252
  Bottom w15: J3.9@1782.82,101.5 1799.9,65 ; J3.9@1799.9,105.3 1799.9,65 ; J3.9 1799.9,65 ; J3.9@1816.98,101.5 1799.9,65 ; v1@2562.56,328.8 2575,265 v1@2587.44,328.8 ; v1(2575,330) 2575,55 2545,25 1839.9,25 1799.9,65
+5VD: J3.10 R24.1 | length 637.8
  Top w20: J3.10 1880,347.8 ; J3.10@1801.3,332.87 1880,347.8 ; J3.10@1801.3,362.73 1880,347.8 ; R24.1 2067.2,535 1880,347.8
A0(+): C1.2 C25.2 J1.10 J4.1 R1.2 | length 2116.8
  Top w20: J4.1@205.87,1521.2 250,1415 ; J4.1@225.15,1527.28 250,1415 ; J4.1 250,948 ; J4.1@274.85,1527.28 250,1415 ; J1.10@288.84,890.42 250,948 ; J4.1@294.13,1521.2 250,1415 ; J1.10@300.3,900.1 250,948 ; J1.10@309.41,912.02 250,948 ; J1.10@385.73,888.55 456.34,839.76 ; J1.10@395.3,900.1 456.34,839.76 ; J1.10@406.74,909.81 456.34,839.76 ; C1.2@511,837 459,837.1 ; C25.2 C1.2 ; C1.2@521,837 596,837 ; R1.2 C1.2 ; 250,948 297.9,900.1 J1.10 396,900.1 459,837.1 ; 459,837.1 515.9,837.1 C1.2
A0(-): C1.1 C26.2 J1.12 J5.1 R2.2 | length 2108.9
  Top w20: J5.1@205.87,178.8 250,285 ; J5.1@225.15,172.72 250,285 ; J5.1 250,748 ; J5.1@274.85,172.72 250,285 ; J1.12@288.49,809.34 250,748 ; J5.1@294.13,178.8 250,285 ; J1.12@300.3,800.1 250,748 ; J1.12@309.95,788.62 250,748 ; J1.12@386.86,787.7 432.1,766 ; J1.12@395.3,800.1 432.1,766 ; J1.12@407.03,809.45 432.1,766 ; 436,767 C1.1@511,767 ; C26.2 C1.1 C1.1@519,767 ; C1.1@521,767 596,767 ; 547.89,767 R2.2 621,767 C1.1@519,767 ; 250,748 302,800 347.7,800 J1.12 398,800.1 432.1,766 ; 432.1,766 433.1,767 C1.1@519,767
AGND: C2.2 C4.1 C5.2 C6.2 C7.1 C11.1 C12.1 C13.1 C14.1 C16.1 C17.2 C18.1 C19.2 C20.1 C21.1 C23.2 C24.1 C25.1 C26.1 J1.1 J1.2 J1.3 J1.4 J1.5 J1.6 J1.7 J1.9 J1.11 J1.13 J1.16 J1.17 J1.18 J1.19 J1.20 J2.4 J2.10 J2.18 J3.5 J3.6 J4.2 J4.3 J4.4 J4.5 J5.2 J5.3 J5.4 J5.5 R18.2 R35.2 U1.5 U2.2 U3.3 U5.2 U6.4 U7.2 U7.3 U7.4 U7.7 | length 5066.2
  Top w11: v1@1465.58,764.49 U1.5@1494.07,815 ; v1@1468.03,768.48 1511.96,808.22 ; v1@1491.94,752.47 1511.96,808.22 ; v1@1493.36,757.01 U1.5@1494.07,815 ; v1@1511.5,759.16 1519.34,813.39 ; v1@1511.64,760.98 1526,812 v1@1540.36,760.98 ; v1@1526,778.32 U1.5 ; v1@1540.03,762.65 1519.34,813.39 ; v1@2669.51,63.48 R35.2@2674.85,116.55 ; v1@2669.64,65.98 2684,117 v1@2698.36,65.98 ; v1@2670.19,68.41 R35.2@2693.15,116.55 ; R35.2@2674.55,118.06 2684,71 R35.2@2693.45,118.06 ; R35.2@2689,119 2726,119 ; R35.2@2690.22,109.58 2726,119 ; R35.2@2690.22,128.42 2726,119 ; v1@2697.81,68.41 R35.2@2674.85,116.55 ; v1@2698.49,63.48 R35.2@2693.15,116.55 ; U7.3@2773.4,137.4 2744,137 ; U7.4 U7.3 ; U7.2@2818.4,163 2858.9,163 ; 2953.9,163 U7.7@2994.4,163 ; U7.7 U7.2 U7.3 ; v1(1479,759) v1@1494.07,772 ; v1(1479,759) U1.5@1494.07,815 ; v1(1479,759) 1511.96,808.22 ; v1@1494.07,772 U1.5@1494.07,815 ; v1@1494.07,772 U1.5 ; U1.5 1526,820.45 v1(1526,759) 1519.34,813.39 ; R35.2@2674.85,116.55 v1(2684,64) ; v1(2684,64) R35.2 2726,119 ; v1(2684,64) R35.2@2693.15,116.55 ; 2726,119 2744,137 ; 2744,137 2795.5,137 U7.3
  Top w15: 889,879 U6.4
  Top w20: v1(516,581) C26.1 ; C25.1 v1(516,1024) ; U3.3 v1(967,1584) ; C6.2 C6.2@1532,1110
  Top w25: U5.2@723,1168 v1(723,1117) U5.2 ; U2.2@1322,1309 v1(1266,1309) U2.2 ; C6.2@1513.65,1111.29 v1(1531,1176) ; C6.2 v1(1531,1176) ; C6.2@1532,1110 v1(1602,1110) ; C6.2@1536,1109 v1(1602,1110) ; C6.2@1538.06,1126.38 v1(1602,1110) ; C6.2@1538.58,1091.69 v1(1602,1110) ; C6.2@1548.35,1111.29 v1(1531,1176)
  Top w30: C12.1 v1(529,1272) ; C4.1 v1(766,1618) ; v1(797,642) C14.1 ; C11.1 v1(799,965) ; R18.2 v1(911,1298) ; C18.1@941,276 v1(871,276) C18.1 v1(946,330) ; C17.2@1140,201 v1(1207,188) 1140,188 C17.2 v1(1140,285) C17.2@1140,211 ; v1(1314,1427) C5.2 ; C13.1@1642,480 v1(1583,480) C13.1 ; C19.2 v1(2161,193) C19.2@2161,107 ; C20.1 v1(2391,218) ; C23.2 608,1215 v1(608,1164) ; C23.2 v1(608,1164) ; C23.2 v1(608,1164) ; v1(1192,1175) v1@1192,1176 ; v1(1192,1175) C7.1 v1@1192,1176 ; v1(1192,1175) 1251,1176 v1@1192,1176 ; C24.1@839,1246 v1(839,1298) C24.1 C24.1@839,1246 ; v1(856,879) 889,879 U6.4 v1(856,879) ; C2.2 v1(1049,882) C2.2 ; v1(1456,689) 1507,689 C16.1 v1(1456,689) ; C21.1 1777,1018 v1(1841,1018) C21.1
AVDD: C2.1 C4.2 C5.1 C17.1 C18.2 C23.1 R23.1 TP1.1 U2.5 U3.1 U5.5 U6.8 | length 3319.6
  Top w15: U6.8@976,742.9 989,748 989,738.4 ; 989,738.4 U6.8 989,738.4
  Top w20: C23.1 U5.5@685,1285 ; C23.1@613.49,1285 U5.5 ; C4.2 870,1482 U3.1 792.99,1482 C4.2@771,1482 ; 846,1481.66 C4.2@771,1482 ; 846,1482 C4.2@771,1482 ; C5.1@1439,1422 U2.5@1439.5,1347 ; C5.1@1439,1432 v1(1439,1488) C5.1 1439.5,1426.5 U2.5 ; U5.5@685,1285 685.5,1285 U5.5 ; U5.5@685,1285 U5.5 ; U5.5@685,1285 612,1285 U5.5
  Top w30: C23.1 v1(607,1340) ; C4.2@761,1482 v1(683,1481) 766,1481 C4.2 ; C18.2@951,206 C17.1 ; TP1.1@1009.56,80.71 C17.1@1030,201 ; TP1.1@1009.59,81.03 C17.1@1032,204 ; TP1.1@1032,80.97 C17.1@1030,201 ; TP1.1@1033.99,56.59 1159.5,79 TP1.1@1033.99,101.41 ; C2.1@1044,758 999,758 ; TP1.1@1054.37,81.44 C17.1@1030,201 ; TP1.1@1054.41,81.03 C17.1@1032,204 ; R23.1 1291,120 1250,79 TP1.1 ; C18.2 945,205 v1(945,141) C18.2 ; C18.2 C17.1 ; 999,758 C2.1 ; 999,758 989,748 976,742.9 999,758 ; C17.1@1030,201 TP1.1 ; C17.1 C17.1@1032,204 ; TP1.1 C17.1@1032,204 ; v1@1049,705 v1(1051,705) ; v1@1049,705 C2.1 ; v1@1049,705 C2.1 ; C2.1 v1(1051,705) ; C2.1 v1(1051,705)
DVDD: C13.2 C19.1 C20.2 C21.2 R22.1 R24.2 R25.2 R26.2 R27.1 R31.1 U1.10 | length 4467.4
  Top w11: U1.10 1702,899.25 1702,901 U1.10@1705,904 ; v1@2130.5,959.98 R27.1@2137.67,1013.48 ; v1@2131.03,963.88 R27.1@2152.33,1013.48 ; R27.1@2135.55,1024.06 v1@2145,977 ; R27.1@2145,1025 v1@2145,977 ; R27.1 v1(2145,960) ; R27.1@2154.45,1024.06 v1@2145,977 ; v1@2158.97,963.88 R27.1@2137.67,1013.48 ; v1@2159.5,959.98 R27.1@2152.33,1013.48 ; v1@2627.51,921.64 R31.1@2632.55,870.94 ; v1@2627.65,918.94 R31.1 ; v1@2628.28,916.31 R31.1@2651.45,870.94 ; v1@2655.72,916.31 R31.1@2632.55,870.94 ; v1@2656.35,918.94 R31.1 ; v1@2656.49,921.64 R31.1@2651.45,870.94 ; R27.1@2137.67,1013.48 v1(2145,960) ; v1(2145,960) R27.1@2152.33,1013.48 ; v1(2145,960) R27.1@2145,1013 ; R27.1@2145,1013 2130.64,961.98 R27.1@2145,1013 ; R27.1@2145,1013 2159.36,961.98 R27.1@2145,1013 ; R31.1@2632.55,870.94 2642,918 R31.1@2651.45,870.94 ; R31.1@2632.55,870.94 v1(2642,921) ; R31.1 v1(2642,921) ; R31.1 v1(2642,921) ; v1(2642,921) R31.1@2651.45,870.94
  Top w20: U1.10 1705,984.01 ; C21.2@1704,1010 1705,934.98 ; C21.2 1705,1014 U1.10@1705,904 ; C19.1@2251.1,109 2270,197.01 ; 2270,235 R26.2@2270,310 ; R26.2@2270,320 2270,395 R25.2@2270,420 ; R25.2@2270,430 2270,505 R24.2@2270,530 ; R24.2 R25.2 R26.2 2270,103 C19.1 ; C19.1@2271,107 2270,197.01 ; C19.1@2290.85,109.44 2270,197.01 ; R25.2@2270,420 2270,345 R25.2@2270,420 ; R24.2@2270,530 2270,455 R24.2@2270,530
  Top w25: R22.1@1647,613 C13.2 R22.1 ; v1@1704,1078 C21.2 v1(1705,1079) ; v1@1704,1078 v1(1705,1079) ; v1@1704,1078 1704,1020 v1(1705,1079)
  Top w30: C13.2 v1(1895,550) 1785,550 ; C13.2@1652,550 1757,550 ; C19.1 2273,102 C19.1@2293,82 ; C20.2@2396,82 v1(2486,82) C20.2 ; C19.1@2293,82 C20.2 ; C19.1@2293,82 2386,82 2271,97 C20.2
VCM: C12.2 J1.8 J1.14 J1.15 R37.2 | length 1938.4
  Top w20: C12.2@524,1150 v1(462,1150) C12.2 538,1141 C12.2@538,1138 ; R37.2 R37.2@578,1098 ; C12.2@538,1138 R37.2@578,1098 ; C12.2@538,1138 578,1089 534,1150 R37.2@578,1098
  Bottom w20: J1.15 203.1,600.1 250,647 ; J1.15@191.26,612.07 250,647 ; J1.15@200.3,600.1 250,647 ; J1.15@211.73,590.39 250,647 ; J1.14@298.06,685.27 250,700.1 ; J1.14@298.06,714.93 250,700.1 ; J1.8@298.06,985.27 250,1000.1 ; J1.8@298.06,1014.93 250,1000.1 ; J1.14@300.3,700.1 250,700.1 ; J1.8@300.3,1000.1 250,1000.1 ; J1.14 250,700.1 ; J1.8 250,1000.1 ; v1(462,1150) 279,1150 250,1119 250,1000.1 ; 250,647 250,700.1 ; 250,700.1 250,1000.1
pads on no net: J2.2 J2.5 J2.6 J2.8 J2.9 J2.11 J2.12 J2.14 J2.19 J3.1 J3.2 J3.3 J3.4 J3.8

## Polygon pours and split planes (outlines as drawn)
AGND on Inner Layer 2 (split plane): 3184.9,475 3184.94,474.83 3184.88,255 3184.89,255 3184.9,15.1 15.1,15.1 15.1,1684.9 3184.9,1684.9
DVDD on Inner Layer 3 (split plane): 3173.95,26.05 1646.05,26.05 1646.05,1673.95 3173.95,1673.95
AVDD on Inner Layer 3 (split plane): 1533.95,26.05 26.05,26.05 26.05,1673.95 1533.95,1673.95

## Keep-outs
Keep-Out Layer:
  the board outline again, w10

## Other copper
Top:
  region net AGND: 1492,820 1455,783 1455,734 1550,734 1550,820 1492,820
Inner Layer 2 (plane layer: these items are gaps in the copper):
  region: 3200,0 0,0 0,1700 3200,1700 hole: 3190,1690 10,1690 10,10 3190,10 3189.98,255 3189.98,255 3190.03,475 3190,475
  lines w10: 3189.98,255 3190.03,475 3190,475 3190,1690 10,1690 10,10 3190,10 3189.98,255 ; 3189.98,255 3189.98,255
Inner Layer 3 (plane layer: these items are gaps in the copper):
  region: 3200,0 0,0 0,1700 3200,1700 hole: 3180,1680 1640,1680 1640,20 3180,20 hole: 1540,1680 20,1680 20,20 1540,20
  lines w12: 20,20 20,1680 1540,1680 1540,20 20,20 ; 1640,20 3180,20 3180,1680 1640,1680 1640,20

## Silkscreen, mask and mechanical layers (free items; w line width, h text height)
Silkscreen Top:
  region: 1368,1386 1406,1386 1406,1346 1368,1346 1368,1386
  region: 647,1250 685,1250 685,1210 647,1210 647,1250
  region: 2855,235 2955,235 2955,215 2855,215 2855,235
  region: 1570,945 1630,945 1630,925 1570,925 1570,945
  lines w12: 3144,54.16 3144,79 3145,79 3145,55 3160,55 3160,91 3161,91 3161,42 3176,42 3176,61 3175,61 3175,41.03 3161,38.03 3161,25 3160,25 3160,50.16 3144,54.16
  text "1" at 2551.43,1636 h30
  text "Rev A" at 2979.87,1621 h40
  text "Texas" at 1830.35,1615.01 h50
  text "CS0" at 2461.72,1581.5 h30
  text "Instruments" at 1962.78,1520.01 h50
  text "(c) 2013" at 1847.23,1422.15 h30
  text "FSX" at 2460.65,1416.5 h30
  text "(MMB0)" at 2424.02,1348.65 h30
  text "TI Design" at 1800.64,1328.39 h40
  text "1" at 24.43,1284 h30
  text "1" at 2335.43,1283 h30
  text "1" at 2733.43,1253 h30
  text "10KSPS 18bit" at 1747.47,1242.05 h40
  text "4Wire" at 2238.23,1218.79 h30
  text "1mW" at 1858.68,1166.5 h35
  text "3Wire" at 2233.23,1015.79 h30
  text "4Wire" at 2098.23,700.29 h30
  text "+5VD" at 2027.01,521 h30
  text "+3.3VD" at 1983.94,411 h30
  text "+1.8VD" at 1991.3,301 h30
  text "1" at 1395.43,11 h30
Silkscreen Bottom:
  lines w12: 60,340 60,1360 430,1360 430,340 60,340 ; 1339,60 1339,431 1859,431 1859,60 1339,60 ; 2760,340 2760,1360 3130,1360 3130,340 2760,340
  text "1" at 35,1285 h30
  text "1" at 2745,1251 h30
  text "1" at 1401,10 h30
Drill Drawing:
  lines w1: 0,0 0.03,0 ; 3200,1700 3200.03,1700 ; 0,1700 0.03,1700 0,1700
  lines w10: -420,0 -50,0 ; -420,1700 -50,1700 ; -370,782.5 -370,0 ; -370,917.5 -370,1700 ; 0,1750 0,1937.68 ; 1413.18,1887.68 0,1887.68 ; 1786.82,1887.68 3200,1887.68 ; 3200,1750 3200,1937.68 ; -370,0 -395,100 -345,100 -370,0 ; -370,1700 -345,1600 -395,1600 -370,1700 ; 0,1887.68 100,1912.68 100,1862.68 0,1887.68 ; 3200,1887.68 3100,1862.68 3100,1912.68 3200,1887.68
  text "3200mil" at 1443.18,1850.18 h50
  text "1700mil" at -516.59,812.5 h50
